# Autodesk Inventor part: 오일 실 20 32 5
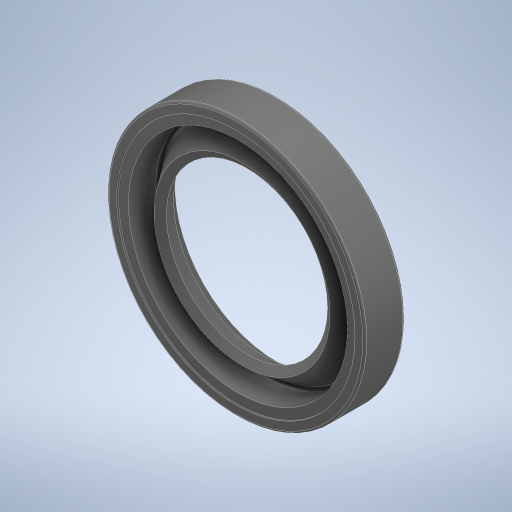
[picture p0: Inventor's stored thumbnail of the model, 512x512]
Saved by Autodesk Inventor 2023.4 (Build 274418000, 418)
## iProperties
Created: 2024-04
Part Number: 오일 실 20 32 5
Material: 고무
Description: 오일 실 - 비스프링, 조립 GA
Document SubType Name: Modeling
Designer: Edu03
Density: 0.93 g/cm^3
Appearance: 기본값
Author: jhkim
Sending System: Autodesk Inventor 2025
Preprocessor: ST-DEVELOPER v20
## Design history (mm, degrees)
feature "Solid1"
node "솔리드1"
